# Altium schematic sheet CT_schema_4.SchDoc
size 212 x 173 mm
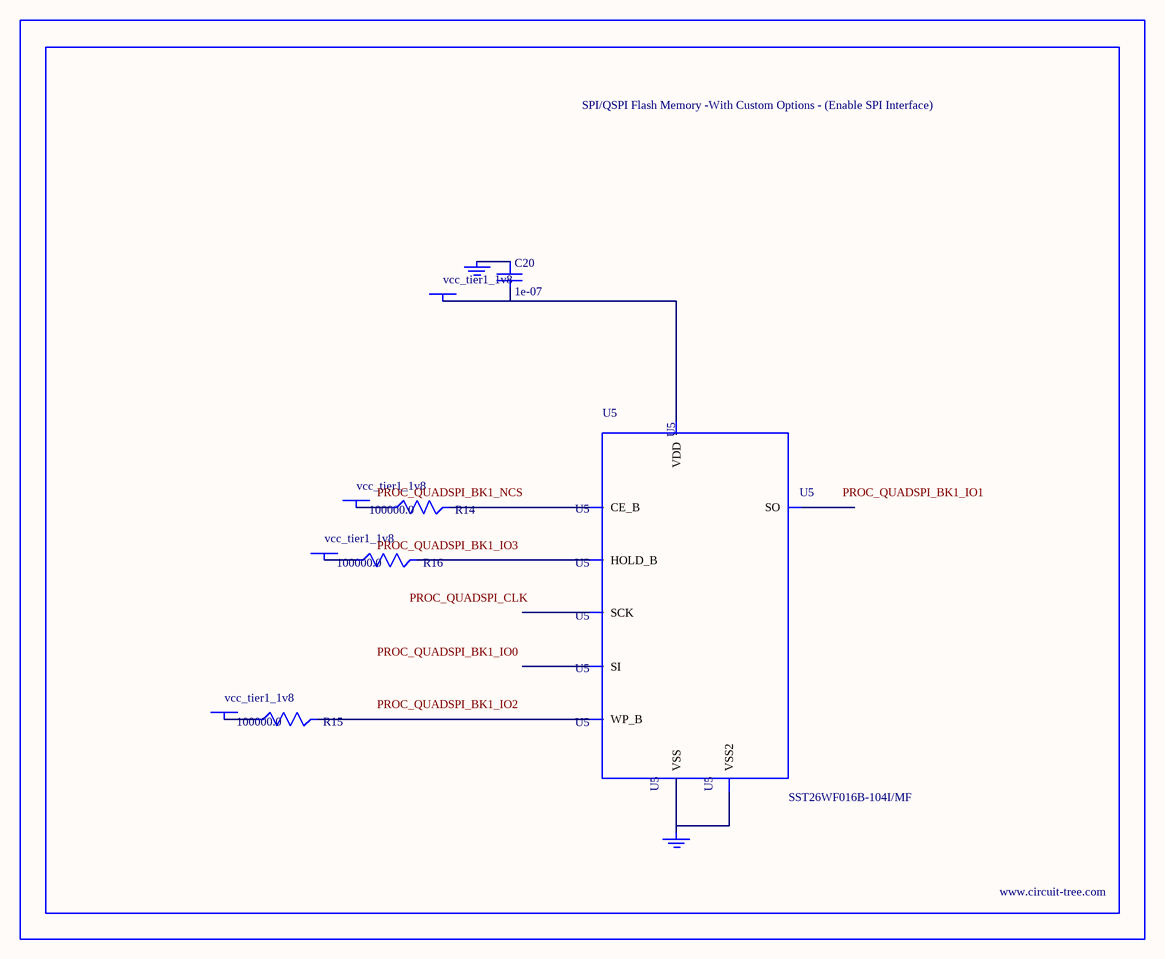
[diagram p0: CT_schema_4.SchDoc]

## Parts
BORDER3  (no value)
C20  1e-07  [C0402]
GND_INSTANCE_3_0  (no value)
GND_INSTANCE_3_1  (no value)
POWER_INSTANCE_3_0  vcc_tier1_1v8
POWER_INSTANCE_3_1  vcc_tier1_1v8
POWER_INSTANCE_3_2  vcc_tier1_1v8
POWER_INSTANCE_3_3  vcc_tier1_1v8
R14  100000.0  [R0603]
R15  100000.0  [R0603]
R16  100000.0  [R0603]
U5  SST26WF016B-104I/MF  [WFDN-8]

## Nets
NetC20_1: C20.1 GND_INSTANCE_3_0.0(GND)
NetC20_2: C20.2 POWER_INSTANCE_3_3.0(PWR) U5.8(VDD)
NetGND_INSTANCE_3_1_0: GND_INSTANCE_3_1.0(GND) U5.4(VSS) U5.9(VSS2)
NetPOWER_INSTANCE_3_0_0: POWER_INSTANCE_3_0.0(PWR) R14.1
NetPOWER_INSTANCE_3_1_0: POWER_INSTANCE_3_1.0(PWR) R15.1
NetPOWER_INSTANCE_3_2_0: POWER_INSTANCE_3_2.0(PWR) R16.1
NetR14_2: R14.2 U5.1(CE_B)
NetR15_2: R15.2 U5.3(WP_B)
NetR16_2: R16.2 U5.7(HOLD_B)

Not connected (* = marked no-connect by the designer): U5 2(SO) 5(SI) 6(SCK)

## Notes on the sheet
- Labels drawn without touching a wire or pin: PROC_QUADSPI_BK1_IO0, PROC_QUADSPI_BK1_IO1, PROC_QUADSPI_BK1_IO2, PROC_QUADSPI_BK1_IO3, PROC_QUADSPI_BK1_NCS, PROC_QUADSPI_CLK

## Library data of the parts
BORDER3 = BORDER_PAGE3
C20 = C0402C104K3RACTU
GND_INSTANCE_3_0 GND_INSTANCE_3_1 = GND
POWER_INSTANCE_3_0-POWER_INSTANCE_3_3 = PWR
R14-R16 = RC0603JR-07100KL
